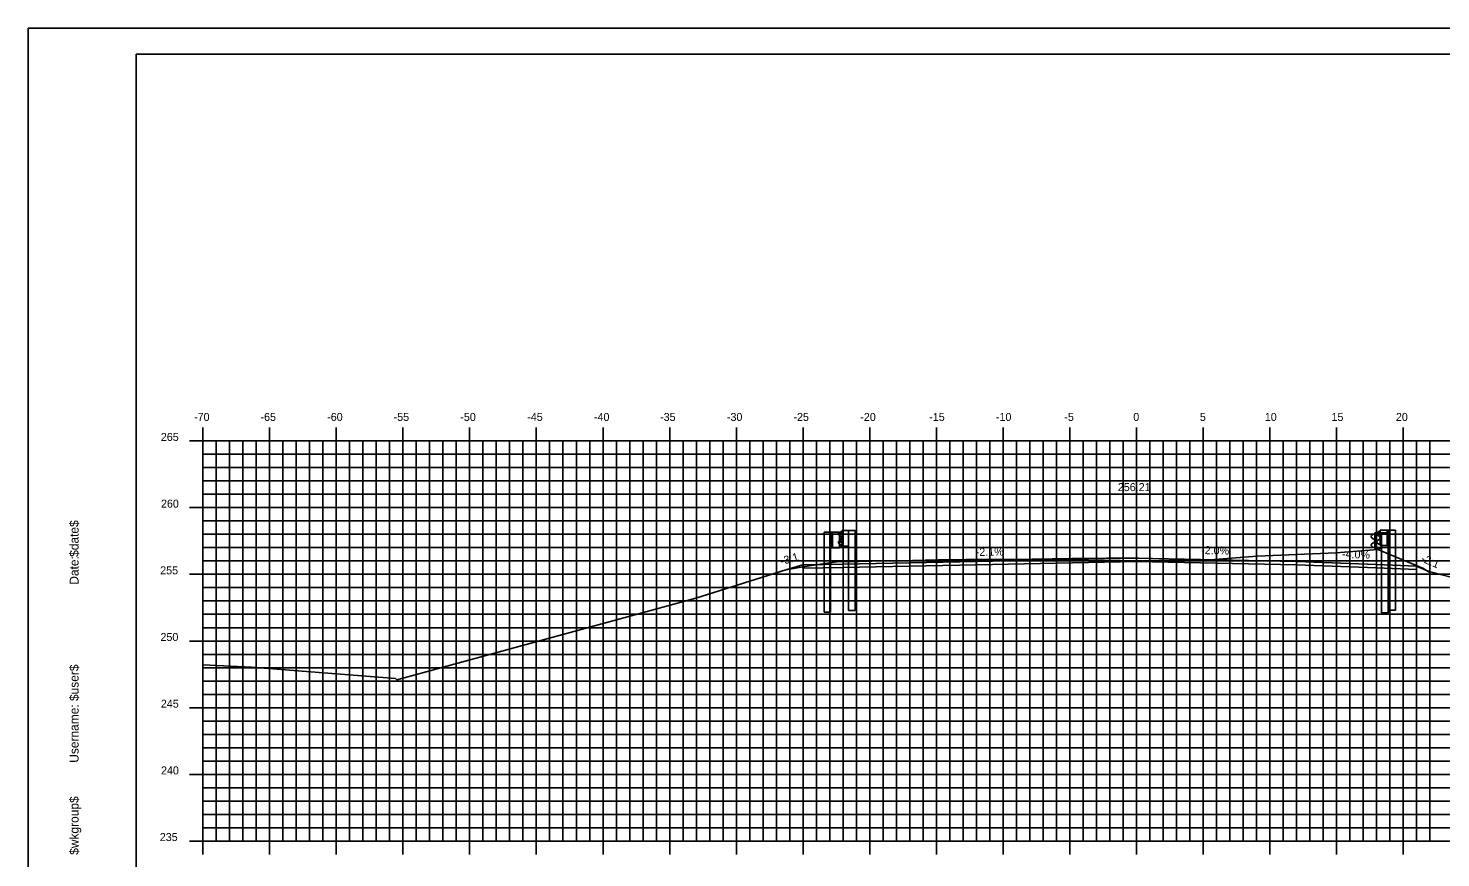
# Model space of a CAD drawing. Extents: x -22 to 1480, y -1511 to 8.
# Drawn here: x -22.2 to 83.8, y -136.7 to -74.5 of the extents above; entities that cross this region are included whole.
import ezdxf

# ---------------------------------------------------------------- set-up
doc = ezdxf.new("R2010")
doc.units = 0
for name, color, linetype in [('ANNOTATION', 7, 'Continuous'), ('BORDER', 7, 'Continuous'), ('D_Guardrail_Beam_Lt', 7, 'Continuous'), ('D_Guardrail_Beam_Rt', 7, 'Continuous'), ('D_Roadway_Centerline', 7, 'Continuous'), ('D_Roadway_Centerline_Text', 7, 'Continuous'), ('D_Roadway_Edge_Shoulder', 7, 'Continuous'), ('D_Roadway_Edge_TW', 7, 'Continuous'), ('H_V ANNOTATION', 7, 'Continuous'), ('MAJOR', 7, 'Continuous'), ('MINOR', 7, 'Continuous'), ('PLOT BOUNDARY', 7, 'Continuous'), ('S_Guardrail_Beam', 7, 'Continuous'), ('S_Roadway_Centerline', 7, 'Continuous')]:
    doc.layers.add(name, color=color, linetype=linetype)

msp = doc.modelspace()

# ---------------------------------------------------------------- linework, layer by layer
at = {"layer": 'BORDER'}
for p, q in [((145.94, -76.47), (-14.06, -76.47)), ((-14.06, -76.47), (-14.06, -181.47))]:
    msp.add_line(p, q, dxfattribs=at)
at = {"layer": 'D_Guardrail_Beam_Lt'}
for p, q in [((79.12, -112.26), (78.98, -112.36)), ((79.21, -112.24), (79.14, -112.25)), ((79.21, -112.15), (79.9, -112.15)), ((79.21, -113.32), (79.21, -112.15)), ((79.73, -112.15), (79.73, -113.32)), ((79.83, -112.15), (79.83, -113.32)), ((79.9, -112.15), (80.37, -112.15)), ((79.9, -112.15), (79.9, -113.32)), ((80.37, -112.15), (80.37, -118.15)), ((78.98, -112.5), (79.17, -112.64)), ((79.17, -112.84), (78.98, -112.97)), ((78.98, -113.12), (79.12, -113.22)), ((79.14, -113.22), (79.21, -113.24)), ((79.21, -112.7), (79.21, -112.77)), ((79.9, -113.32), (79.21, -113.32)), ((79.88, -118.15), (79.88, -113.32)), ((79.88, -118.15), (80.37, -118.15))]:
    msp.add_line(p, q, dxfattribs=at)
for centre, major_axis, start_param, end_param in [((79.14, -112.29), (-0.0417, 0), 4.907132, 5.323254), ((79.03, -112.43), (-0.0877, 0), 5.323254, 7.243116), ((79.03, -113.04), (-0.0877, 0), 5.323254, 7.243116), ((79.14, -113.18), (-0.0417, 0), 0.959931, 1.376053), ((79.13, -112.7), (0.0789, 0), 0, 0.959931), ((79.13, -112.77), (0.0789, 0), 5.323254, 6.283185)]:
    msp.add_ellipse(centre, major_axis=major_axis, ratio=0.995501, start_param=start_param, end_param=end_param, dxfattribs=at)
at = {"layer": 'D_Guardrail_Beam_Rt'}
for p, q in [((37.51, -112.31), (37.51, -118.31)), ((37.98, -112.31), (37.51, -112.31)), ((38.67, -112.31), (37.98, -112.31)), ((37.98, -112.31), (37.98, -113.48)), ((38.04, -112.31), (38.04, -113.48)), ((38.15, -112.31), (38.15, -113.48)), ((38.67, -113.48), (38.67, -112.31)), ((38.67, -112.4), (38.74, -112.41)), ((38.67, -112.86), (38.67, -112.93)), ((38.9, -112.66), (38.71, -112.8)), ((38.71, -113), (38.9, -113.13)), ((38.76, -112.42), (38.9, -112.52)), ((38.9, -113.28), (38.76, -113.38)), ((37.98, -113.48), (38.67, -113.48)), ((38, -118.31), (38, -113.48)), ((38.74, -113.38), (38.67, -113.4)), ((38, -118.31), (37.51, -118.31))]:
    msp.add_line(p, q, dxfattribs=at)
for centre, major_axis, start_param, end_param in [((38.75, -112.86), (-0.0789, 0), 5.323254, 6.283185), ((38.75, -112.93), (-0.0789, 0), 6.283185, 7.243116), ((38.73, -112.45), (0.0417, 0), 0.959931, 1.376053), ((38.85, -112.59), (0.0877, 0), 5.323254, 7.243116), ((38.85, -113.2), (0.0877, 0), 5.323254, 7.243116), ((38.73, -113.34), (0.0417, 0), 4.907132, 5.323254)]:
    msp.add_ellipse(centre, major_axis=major_axis, ratio=0.995501, start_param=start_param, end_param=end_param, dxfattribs=at)
at = {"layer": 'D_Roadway_Centerline'}
msp.add_lwpolyline([(34.64, -115.14), (35.93, -114.77), (38.93, -114.71), (48.94, -114.5), (60.94, -114.26), (72.94, -114.5), (78.94, -114.74), (81.94, -114.86), (82.99, -115.31)], dxfattribs=at)
at = {"layer": 'D_Roadway_Edge_Shoulder'}
for points in [[(48.94, -114.5), (38.93, -114.71), (38.93, -114.71), (35.93, -114.77), (35.93, -115.02), (38.93, -114.96), (38.93, -114.96), (48.93, -114.75)], [(72.94, -114.5), (78.94, -114.74), (78.94, -114.74), (81.94, -114.86), (81.94, -115.11), (78.94, -114.99), (78.94, -114.99), (72.94, -114.75)]]:
    msp.add_lwpolyline(points, close=True, dxfattribs=at)
at = {"layer": 'D_Roadway_Edge_TW'}
msp.add_lwpolyline([(72.94, -114.75), (72.94, -114.5), (60.94, -114.26), (48.94, -114.5), (48.94, -114.75), (60.94, -114.51)], close=True, dxfattribs=at)
at = {"layer": 'MAJOR'}
for p, q in [((-9.06, -104.46), (-9.06, -105.47)), ((-4.06, -104.46), (-4.06, -105.47)), ((0.94, -104.46), (0.94, -105.47)), ((5.94, -104.46), (5.94, -105.47)), ((10.94, -104.46), (10.94, -105.47)), ((15.94, -104.46), (15.94, -105.47)), ((20.94, -104.46), (20.94, -105.47)), ((25.94, -104.46), (25.94, -105.47)), ((30.94, -104.46), (30.94, -105.47)), ((35.94, -104.46), (35.94, -105.47)), ((40.94, -104.46), (40.94, -105.47)), ((45.94, -104.46), (45.94, -105.47)), ((50.94, -104.46), (50.94, -105.47)), ((55.94, -104.46), (55.94, -105.47)), ((60.94, -104.46), (60.94, -105.47)), ((65.94, -104.46), (65.94, -105.47)), ((70.94, -104.46), (70.94, -105.47)), ((75.94, -104.46), (75.94, -105.47)), ((80.94, -104.46), (80.94, -105.47)), ((-10.06, -105.47), (-9.06, -105.47)), ((-9.06, -105.47), (130.94, -105.47)), ((-9.06, -135.47), (-9.06, -105.47)), ((-9.06, -135.47), (-9.06, -105.47)), ((-9.06, -105.47), (130.94, -105.47)), ((-4.06, -135.47), (-4.06, -105.47)), ((0.94, -135.47), (0.94, -105.47)), ((5.94, -135.47), (5.94, -105.47)), ((10.94, -135.47), (10.94, -105.47)), ((15.94, -135.47), (15.94, -105.47)), ((20.94, -135.47), (20.94, -105.47)), ((25.94, -135.47), (25.94, -105.47)), ((30.94, -135.47), (30.94, -105.47)), ((35.94, -135.47), (35.94, -105.47)), ((40.94, -135.47), (40.94, -105.47)), ((45.94, -135.47), (45.94, -105.47)), ((50.94, -135.47), (50.94, -105.47)), ((55.94, -135.47), (55.94, -105.47)), ((60.94, -135.47), (60.94, -105.47)), ((65.94, -135.47), (65.94, -105.47)), ((70.94, -135.47), (70.94, -105.47)), ((75.94, -135.47), (75.94, -105.47)), ((80.94, -135.47), (80.94, -105.47)), ((-10.06, -110.47), (-9.06, -110.47)), ((-9.06, -110.47), (130.94, -110.47)), ((-10.06, -115.47), (-9.06, -115.47)), ((-9.06, -115.47), (130.94, -115.47)), ((-10.06, -120.47), (-9.06, -120.47)), ((-9.06, -120.47), (130.94, -120.47)), ((-10.06, -125.47), (-9.06, -125.47)), ((-9.06, -125.47), (130.94, -125.47)), ((-10.06, -130.47), (-9.06, -130.47)), ((-9.06, -130.47), (130.94, -130.47)), ((-10.06, -135.47), (-9.06, -135.47)), ((-9.06, -135.47), (130.94, -135.47)), ((-9.06, -135.47), (130.94, -135.47)), ((-9.06, -136.47), (-9.06, -135.47)), ((-4.06, -136.47), (-4.06, -135.47)), ((0.94, -136.47), (0.94, -135.47)), ((5.94, -136.47), (5.94, -135.47)), ((10.94, -136.47), (10.94, -135.47)), ((15.94, -136.47), (15.94, -135.47)), ((20.94, -136.47), (20.94, -135.47)), ((25.94, -136.47), (25.94, -135.47)), ((30.94, -136.47), (30.94, -135.47)), ((35.94, -136.47), (35.94, -135.47)), ((40.94, -136.47), (40.94, -135.47)), ((45.94, -136.47), (45.94, -135.47)), ((50.94, -136.47), (50.94, -135.47)), ((55.94, -136.47), (55.94, -135.47)), ((60.94, -136.47), (60.94, -135.47)), ((65.94, -136.47), (65.94, -135.47)), ((70.94, -136.47), (70.94, -135.47)), ((75.94, -136.47), (75.94, -135.47)), ((80.94, -136.47), (80.94, -135.47))]:
    msp.add_line(p, q, dxfattribs=at)
at = {"layer": 'MINOR'}
for p, q in [((-8.06, -135.47), (-8.06, -105.47)), ((-7.06, -135.47), (-7.06, -105.47)), ((-6.06, -135.47), (-6.06, -105.47)), ((-5.06, -135.47), (-5.06, -105.47)), ((-3.06, -135.47), (-3.06, -105.47)), ((-2.06, -135.47), (-2.06, -105.47)), ((-1.06, -135.47), (-1.06, -105.47)), ((-0.06, -135.47), (-0.06, -105.47)), ((1.94, -135.47), (1.94, -105.47)), ((2.94, -135.47), (2.94, -105.47)), ((3.94, -135.47), (3.94, -105.47)), ((4.94, -135.47), (4.94, -105.47)), ((6.94, -135.47), (6.94, -105.47)), ((7.94, -135.47), (7.94, -105.47)), ((8.94, -135.47), (8.94, -105.47)), ((9.94, -135.47), (9.94, -105.47)), ((11.94, -135.47), (11.94, -105.47)), ((12.94, -135.47), (12.94, -105.47)), ((13.94, -135.47), (13.94, -105.47)), ((14.94, -135.47), (14.94, -105.47)), ((16.94, -135.47), (16.94, -105.47)), ((17.94, -135.47), (17.94, -105.47)), ((18.94, -135.47), (18.94, -105.47)), ((19.94, -135.47), (19.94, -105.47)), ((21.94, -135.47), (21.94, -105.47)), ((22.94, -135.47), (22.94, -105.47)), ((23.94, -135.47), (23.94, -105.47)), ((24.94, -135.47), (24.94, -105.47)), ((26.94, -135.47), (26.94, -105.47)), ((27.94, -135.47), (27.94, -105.47)), ((28.94, -135.47), (28.94, -105.47)), ((29.94, -135.47), (29.94, -105.47)), ((31.94, -135.47), (31.94, -105.47)), ((32.94, -135.47), (32.94, -105.47)), ((33.94, -135.47), (33.94, -105.47)), ((34.94, -135.47), (34.94, -105.47)), ((36.94, -135.47), (36.94, -105.47)), ((37.94, -135.47), (37.94, -105.47)), ((38.94, -135.47), (38.94, -105.47)), ((39.94, -135.47), (39.94, -105.47)), ((41.94, -135.47), (41.94, -105.47)), ((42.94, -135.47), (42.94, -105.47)), ((43.94, -135.47), (43.94, -105.47)), ((44.94, -135.47), (44.94, -105.47)), ((46.94, -135.47), (46.94, -105.47)), ((47.94, -135.47), (47.94, -105.47)), ((48.94, -135.47), (48.94, -105.47)), ((49.94, -135.47), (49.94, -105.47)), ((51.94, -135.47), (51.94, -105.47)), ((52.94, -135.47), (52.94, -105.47)), ((53.94, -135.47), (53.94, -105.47)), ((54.94, -135.47), (54.94, -105.47)), ((56.94, -135.47), (56.94, -105.47)), ((57.94, -135.47), (57.94, -105.47)), ((58.94, -135.47), (58.94, -105.47)), ((59.94, -135.47), (59.94, -105.47)), ((61.94, -135.47), (61.94, -105.47)), ((62.94, -135.47), (62.94, -105.47)), ((63.94, -135.47), (63.94, -105.47)), ((64.94, -135.47), (64.94, -105.47)), ((66.94, -135.47), (66.94, -105.47)), ((67.94, -135.47), (67.94, -105.47)), ((68.94, -135.47), (68.94, -105.47)), ((69.94, -135.47), (69.94, -105.47)), ((71.94, -135.47), (71.94, -105.47)), ((72.94, -135.47), (72.94, -105.47)), ((73.94, -135.47), (73.94, -105.47)), ((74.94, -135.47), (74.94, -105.47)), ((76.94, -135.47), (76.94, -105.47)), ((77.94, -135.47), (77.94, -105.47)), ((78.94, -135.47), (78.94, -105.47)), ((79.94, -135.47), (79.94, -105.47)), ((81.94, -135.47), (81.94, -105.47)), ((82.94, -135.47), (82.94, -105.47)), ((-9.06, -106.47), (130.94, -106.47)), ((-9.06, -106.47), (-8.06, -106.47)), ((-9.06, -107.47), (130.94, -107.47)), ((-9.06, -107.47), (-8.06, -107.47)), ((-9.06, -108.47), (130.94, -108.47)), ((-9.06, -108.47), (-8.06, -108.47)), ((-9.06, -109.47), (130.94, -109.47)), ((-9.06, -109.47), (-8.06, -109.47)), ((-9.06, -111.47), (130.94, -111.47)), ((-9.06, -111.47), (-8.06, -111.47)), ((-9.06, -112.47), (130.94, -112.47)), ((-9.06, -112.47), (-8.06, -112.47)), ((-9.06, -113.47), (130.94, -113.47)), ((-9.06, -113.47), (-8.06, -113.47)), ((-9.06, -114.47), (130.94, -114.47)), ((-9.06, -114.47), (-8.06, -114.47)), ((-9.06, -116.47), (130.94, -116.47)), ((-9.06, -116.47), (-8.06, -116.47)), ((-9.06, -117.47), (130.94, -117.47)), ((-9.06, -117.47), (-8.06, -117.47)), ((-9.06, -118.47), (130.94, -118.47)), ((-9.06, -118.47), (-8.06, -118.47)), ((-9.06, -119.47), (130.94, -119.47)), ((-9.06, -119.47), (-8.06, -119.47)), ((-9.06, -121.47), (130.94, -121.47)), ((-9.06, -121.47), (-8.06, -121.47)), ((-9.06, -122.47), (130.94, -122.47)), ((-9.06, -122.47), (-8.06, -122.47)), ((-9.06, -123.47), (130.94, -123.47)), ((-9.06, -123.47), (-8.06, -123.47)), ((-9.06, -124.47), (130.94, -124.47)), ((-9.06, -124.47), (-8.06, -124.47)), ((-9.06, -126.47), (130.94, -126.47)), ((-9.06, -126.47), (-8.06, -126.47)), ((-9.06, -127.47), (130.94, -127.47)), ((-9.06, -127.47), (-8.06, -127.47)), ((-9.06, -128.47), (130.94, -128.47)), ((-9.06, -128.47), (-8.06, -128.47)), ((-9.06, -129.47), (130.94, -129.47)), ((-9.06, -129.47), (-8.06, -129.47)), ((-9.06, -131.47), (130.94, -131.47)), ((-9.06, -131.47), (-8.06, -131.47)), ((-9.06, -132.47), (130.94, -132.47)), ((-9.06, -132.47), (-8.06, -132.47)), ((-9.06, -133.47), (130.94, -133.47)), ((-9.06, -133.47), (-8.06, -133.47)), ((-9.06, -134.47), (130.94, -134.47)), ((-9.06, -134.47), (-8.06, -134.47))]:
    msp.add_line(p, q, dxfattribs=at)
at = {"layer": 'PLOT BOUNDARY'}
msp.add_lwpolyline([(-22.15, -184.53), (147.85, -184.53), (147.85, -74.53), (-22.15, -74.53)], close=True, dxfattribs=at)
at = {"layer": 'S_Guardrail_Beam'}
for p, q in [((38.86, -112.25), (38.78, -112.27)), ((38.86, -112.18), (39.35, -112.18)), ((38.86, -113.35), (38.86, -112.18)), ((39.35, -112.18), (39.84, -112.18)), ((39.35, -112.18), (39.35, -113.35)), ((39.84, -112.18), (39.84, -118.18)), ((38.76, -112.28), (38.62, -112.38)), ((38.62, -112.52), (38.81, -112.66)), ((38.81, -112.87), (38.62, -113.01)), ((38.62, -113.15), (38.76, -113.25)), ((38.78, -113.26), (38.86, -113.28)), ((38.85, -112.72), (38.85, -112.81)), ((78.72, -112.47), (78.57, -112.57)), ((78.57, -112.71), (78.77, -112.85)), ((78.77, -113.07), (78.57, -113.2)), ((78.82, -112.45), (78.73, -112.46)), ((78.8, -112.91), (78.8, -113)), ((78.82, -112.37), (79.31, -112.37)), ((78.82, -113.54), (78.82, -112.37)), ((79.31, -112.37), (79.8, -112.37)), ((79.31, -112.37), (79.31, -113.54)), ((79.8, -112.37), (79.8, -118.37)), ((39.35, -113.35), (38.86, -113.35)), ((39.35, -118.18), (39.35, -113.35)), ((78.57, -113.35), (78.72, -113.45)), ((78.73, -113.45), (78.82, -113.47)), ((79.31, -113.54), (78.82, -113.54)), ((79.31, -118.37), (79.31, -113.54)), ((39.35, -118.18), (39.84, -118.18)), ((79.31, -118.37), (79.8, -118.37))]:
    msp.add_line(p, q, dxfattribs=at)
for centre, major_axis, start_param, end_param in [((38.67, -112.45), (-0.0877, 0), 5.323254, 7.243116), ((38.67, -113.08), (-0.0877, 0), 5.323254, 7.243116), ((38.78, -112.31), (-0.0417, 0), 4.886922, 5.323254), ((38.78, -113.22), (-0.0417, 0), 0.959931, 1.396263), ((38.77, -112.72), (0.0789, 0), 0, 0.959931), ((38.77, -112.81), (0.0789, 0), 5.323254, 6.283185), ((78.62, -112.64), (-0.0877, 0), 5.323254, 7.243116), ((78.62, -113.27), (-0.0877, 0), 5.323254, 7.243116), ((78.74, -112.5), (-0.0417, 0), 4.886922, 5.323254), ((78.72, -112.91), (0.0789, 0), 0, 0.959931), ((78.72, -113), (0.0789, 0), 5.323254, 6.283185), ((78.74, -113.41), (-0.0417, 0), 0.959931, 1.396263)]:
    msp.add_ellipse(centre, major_axis=major_axis, ratio=0.995501, start_param=start_param, end_param=end_param, dxfattribs=at)
at = {"layer": 'S_Roadway_Centerline'}
msp.add_lwpolyline([(-9.06, -122.25), (-5.41, -122.44), (5.37, -123.28), (5.47, -123.37), (27.91, -117.27), (34.64, -115.14), (36.06, -114.88), (37.43, -114.68), (38.65, -114.52), (40.14, -114.5), (41.09, -114.48), (43.18, -114.45), (46.09, -114.39), (48.14, -114.37), (51.09, -114.36), (53.11, -114.34), (56.09, -114.29), (58.68, -114.27), (60.65, -114.26), (61.09, -114.27), (64.16, -114.35), (66.09, -114.42), (66.13, -114.42), (69.98, -114.1), (75.92, -113.85), (79.03, -113.61), (82.46, -115.03), (82.84, -115.28), (82.92, -115.29), (83.06, -115.32), (84.81, -115.77)], dxfattribs=at)

# ---------------------------------------------------------------- texts
at = {"layer": 'ANNOTATION'}
for s, rotation, p in [('-3:1', 16.0578, (34.33, -114.79)), ('-2.1%', 1.1692, (48.89, -114.1)), ('-2.0%', 358.8542, (65.78, -113.95)), ('-4.0%', 357.7094, (76.34, -114.23)), ('-2:1', 336.8601, (82.22, -114.49))]:
    msp.add_text(s, height=0.6, rotation=rotation, dxfattribs=at).set_placement(p)
at = {"layer": 'BORDER'}
for s, p in [('$date$', (-18.38, -114.16)), ('Date:', (-18.38, -116.25)), ('$user$', (-18.38, -124.97)), ('Username:', (-18.38, -129.6)), ('$wkgroup$', (-18.38, -136.5))]:
    msp.add_text(s, height=0.67, rotation=90, dxfattribs=at).set_placement(p)
at = {"layer": 'D_Roadway_Centerline'}
for s, p in [('C', (60.93, -114.26)), ('L', (60.94, -114.26))]:
    msp.add_text(s, height=0.0146, dxfattribs=at).set_placement(p)
at = {"layer": 'D_Roadway_Centerline_Text'}
msp.add_text('256.21', height=0.6, dxfattribs=at).set_placement((59.54, -109.23))
at = {"layer": 'H_V ANNOTATION'}
for s, p in [('-70', (-9.72, -103.97)), ('-65', (-4.74, -103.97)), ('-60', (0.26, -103.97)), ('-55', (5.24, -103.97)), ('-50', (10.24, -103.97)), ('-45', (15.26, -103.97)), ('-40', (20.26, -103.97)), ('-35', (25.22, -103.97)), ('-30', (30.23, -103.97)), ('-25', (35.22, -103.97)), ('-20', (40.23, -103.97)), ('-15', (45.4, -103.97)), ('-10', (50.4, -103.97)), ('-5', (55.53, -103.97)), ('0', (60.7, -103.97)), ('5', (65.69, -103.97)), ('10', (70.56, -103.97)), ('15', (75.56, -103.97)), ('20', (80.39, -103.97)), ('265', (-12.21, -105.47)), ('260', (-12.2, -110.47)), ('255', (-12.26, -115.47)), ('250', (-12.24, -120.47)), ('245', (-12.21, -125.47)), ('240', (-12.2, -130.47)), ('235', (-12.29, -135.47))]:
    msp.add_text(s, height=0.6, dxfattribs=at).set_placement(p)

doc.saveas('drawing.dxf')
